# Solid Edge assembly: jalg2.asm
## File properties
Author: Mac
Template: Normal.asm
Last saved by: Mac
Revision: 8
Application: Solid Edge
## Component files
jala_kinnitus.par
mootorijalg2.par
kruvi mutter.par
kruvi4.par
polt.asm
kruvi3.par
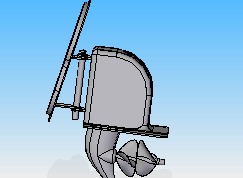
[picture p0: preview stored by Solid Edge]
